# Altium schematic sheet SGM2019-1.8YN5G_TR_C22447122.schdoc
size 127 x 101 mm
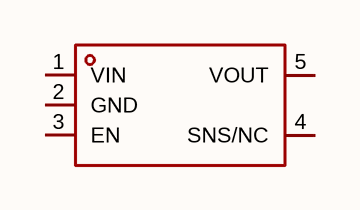
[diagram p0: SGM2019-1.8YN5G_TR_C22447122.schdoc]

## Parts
U?  jsm2019-1.8yn5g/tr  [SOT-23-5_L3.0-W1.7-P0.95-LS2.8-BR]  (value not drawn)

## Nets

Not connected (* = marked no-connect by the designer): U? 1(VIN) 2(GND) 3(EN) 4(SNS/NC) 5(VOUT)

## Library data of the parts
U? = jsm2019-1.8yn5g/tr: 输出极性:正极;工作电压:5.5V;输出电压:1.8V;输出电流:300mA;电源纹波抑制比(PSRR):80dB@(100Hz);输出类型:固定;; Manufacturer: JSMSEMI(杰盛微); Symbol: SGM2019-1.8YN5G/TR_C22447122; AddInBom: yes; ModelId: 0a2a1b8f50944f73965918ad6e5fe167; ModelName: SOT-23-5_L2.9-W1.6-H1.1-LS2.8-P0.95; ModelTransform: 114.173,109.636,0,180,0,0,0,0,0; Output Configuration: 正极; Voltage - Supply: 5.5V; Output Voltage: 1.8V; Output Current: 300mA; Voltage Dropout: 250mV@(300mA); standby current: 2uA; Output Type: 固定; Number of Outputs: 1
